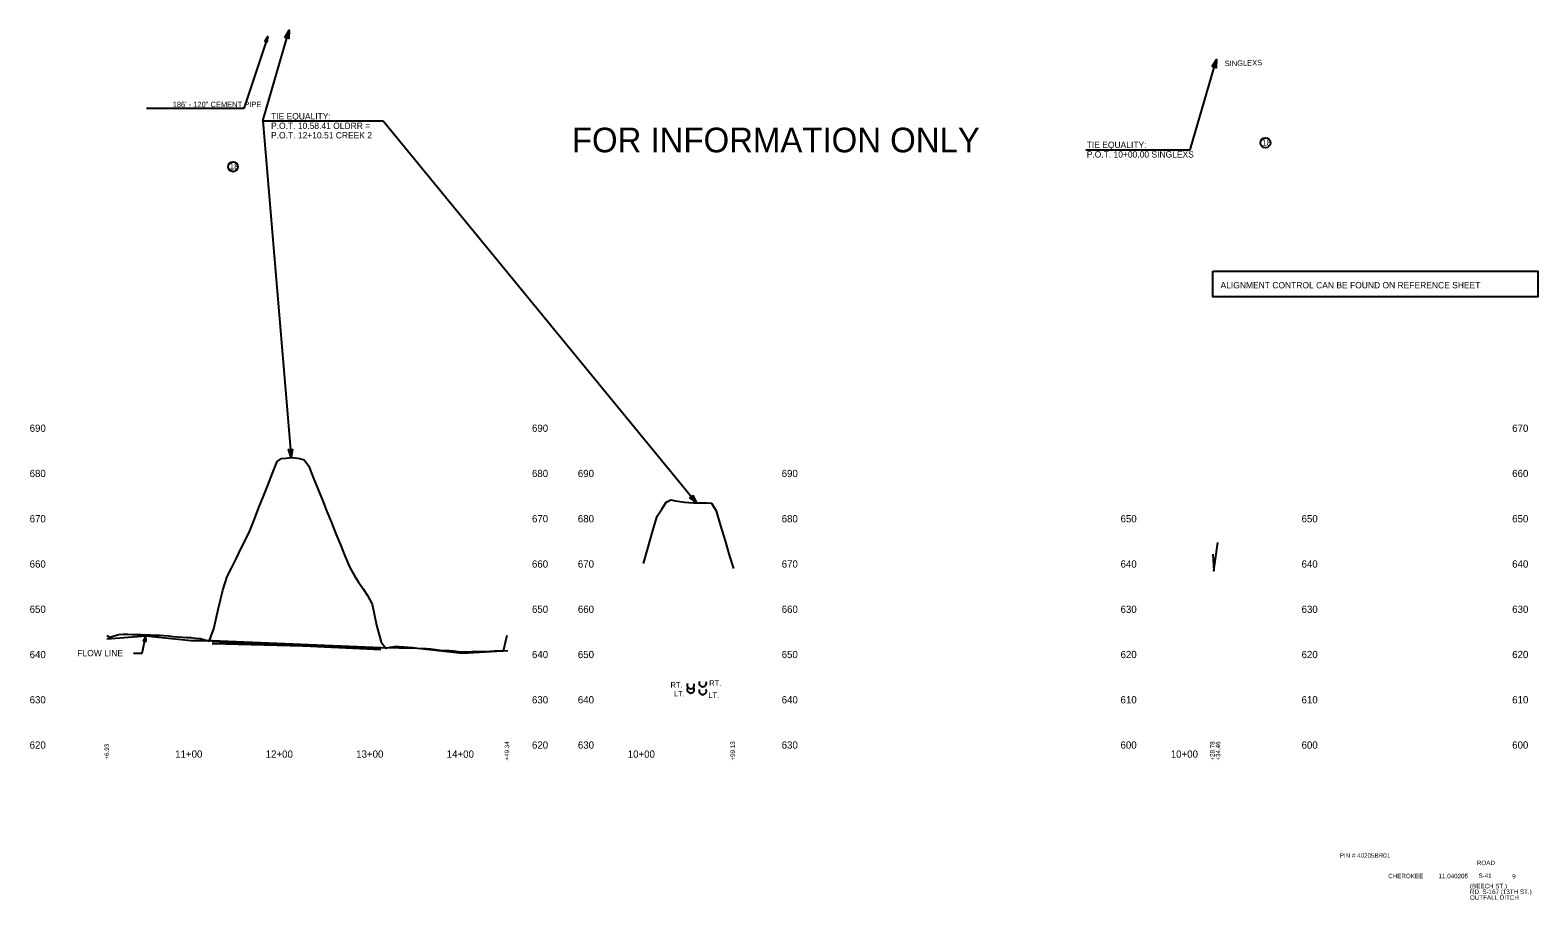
# Model space of a CAD drawing. Extents: x 16382402 to 16388022, y 46194326 to 46202918.
# Drawn here: x 16384274 to 16385939, y 46198905 to 46199866 of the extents above; entities that cross this region are included whole.
import ezdxf

# ---------------------------------------------------------------- set-up
doc = ezdxf.new("R2010")
doc.units = 0
for name, color, linetype in [('Default', 7, 'Continuous'), ('RD_DDB_ElevTX', 7, 'Continuous'), ('RD_DDB_Profile_EX', 7, 'Continuous'), ('RD_DDB_Profile_Lbl', 7, 'Continuous'), ('RD_DDB_StaTX', 7, 'Continuous'), ('RD_EX_DR_Pipe', 7, 'Continuous'), ('RD_EX_DV_Prop', 7, 'Continuous'), ('RD_EX_Misc', 7, 'Continuous'), ('RD_HC_Data', 7, 'Continuous'), ('RD_PD_Final_TX', 7, 'Continuous'), ('RD_Sketch1', 7, 'Continuous'), ('RD_TX_Drainage', 7, 'Continuous'), ('RD_TX_Misc1', 7, 'Continuous'), ('RD_TX_RoadID', 7, 'Continuous')]:
    doc.layers.add(name, color=color, linetype=linetype)

msp = doc.modelspace()

# ---------------------------------------------------------------- linework, layer by layer
at = {"layer": 'Default'}
for centre in [(16385003.4, 46199142), (16385016.7, 46199144.1), (16385003.4, 46199137.1), (16385016.7, 46199135.5)]:
    msp.add_arc(centre, 3.98, 153.828, 22.5332, dxfattribs=at)
at = {"layer": 'RD_DDB_Profile_EX'}
for points in [[(16384358.3, 46199196.8), (16384361.4, 46199195.1), (16384366.4, 46199196.5), (16384371.4, 46199197.9), (16384376.4, 46199198.4), (16384381.4, 46199198.1), (16384386.4, 46199197.8), (16384391.4, 46199197.8), (16384396.4, 46199197.8), (16384401.4, 46199197.7), (16384406.4, 46199197.5), (16384411.4, 46199197.3), (16384416.4, 46199197), (16384421.4, 46199196.7), (16384426.4, 46199196.3), (16384431.4, 46199195.7), (16384436.4, 46199195.2), (16384441.4, 46199194.9), (16384446.4, 46199194.7), (16384451.4, 46199194.5), (16384456.4, 46199194), (16384461.4, 46199193.4), (16384466.4, 46199192.2), (16384471.4, 46199190.6), (16384476.4, 46199204), (16384481.4, 46199225.5), (16384486.4, 46199247), (16384491.4, 46199261.8), (16384496.4, 46199272), (16384501.4, 46199282.2), (16384506.4, 46199292.4), (16384511.4, 46199302.6), (16384516.4, 46199312.6), (16384521.4, 46199325.4), (16384526.4, 46199338.1), (16384531.4, 46199350.9), (16384536.4, 46199363.6), (16384541.4, 46199376.3), (16384546.4, 46199389.2), (16384551.4, 46199392.3), (16384556.4, 46199392.8), (16384561.4, 46199393.4), (16384566.4, 46199392.9), (16384571.4, 46199392.2), (16384576.4, 46199390.9), (16384581.4, 46199383.7), (16384586.4, 46199371.3), (16384591.4, 46199358.8), (16384596.4, 46199346.4), (16384601.4, 46199333.9), (16384606.4, 46199321.5), (16384611.4, 46199309.2), (16384616.4, 46199297), (16384621.4, 46199284.8), (16384626.4, 46199272.6), (16384631.4, 46199263.3), (16384636.4, 46199255.9), (16384641.4, 46199248.5), (16384646.4, 46199240.9), (16384651.4, 46199231.4), (16384656.4, 46199208.4), (16384661.4, 46199189.6), (16384666.4, 46199182.9), (16384671.4, 46199183.8), (16384676.4, 46199184.6), (16384681.4, 46199184.7), (16384686.4, 46199184.4), (16384691.4, 46199184), (16384696.4, 46199183.4), (16384701.4, 46199182.9), (16384706.4, 46199182.5), (16384711.4, 46199182.3), (16384716.4, 46199181.9), (16384721.4, 46199181.3), (16384726.4, 46199180.7), (16384731.4, 46199180.4), (16384736.4, 46199180.2), (16384741.4, 46199179.9), (16384746.4, 46199179.2), (16384751.4, 46199178.6), (16384756.4, 46199178.9), (16384761.4, 46199179.3), (16384766.4, 46199179.4), (16384771.4, 46199179.3), (16384776.4, 46199179.3), (16384781.4, 46199179.5), (16384786.4, 46199179.9), (16384791.4, 46199180), (16384796.4, 46199179.9), (16384800.7, 46199197.3)], [(16384951.4, 46199276.2), (16384956.4, 46199294.5), (16384961.4, 46199312.9), (16384966.4, 46199328.8), (16384971.4, 46199336.5), (16384976.4, 46199344.2), (16384981.4, 46199346.5), (16384986.4, 46199345.7), (16384991.4, 46199344.9), (16384996.4, 46199344.1), (16385001.4, 46199343.6), (16385006.4, 46199343.5), (16385011.4, 46199343.4), (16385016.4, 46199343.3), (16385021.4, 46199343.2), (16385026.4, 46199343.1), (16385031.4, 46199334.5), (16385036.4, 46199317.9), (16385041.4, 46199301.3), (16385046.4, 46199284.6), (16385050.5, 46199270.9)], [(16385580.1, 46199286.7), (16385581.4, 46199268.2), (16385585.8, 46199299.5)], [(16384358.3, 46199193), (16384401.4, 46199196.3), (16384451.4, 46199191.2), (16384474.5, 46199191.2), (16384661.1, 46199183.4), (16384701.4, 46199182.9), (16384751.4, 46199177.2), (16384801.4, 46199180.1)]]:
    msp.add_lwpolyline(points, dxfattribs=at)
at = {"layer": 'RD_EX_DR_Pipe'}
for p, q in [((16384474.5, 46199190.1), (16384661.1, 46199181.5)), ((16384474.5, 46199188.1), (16384661.1, 46199183.2))]:
    msp.add_line(p, q, dxfattribs=at)
at = {"layer": 'RD_EX_DV_Prop'}
for centre in [(16385638.4, 46199741.1), (16384497.7, 46199714.7)]:
    msp.add_circle(centre, 5.49, dxfattribs=at)
at = {"layer": 'RD_HC_Data'}
for p, q in [((16384530.5, 46199765.5), (16384559.8, 46199865.5)), ((16385555.1, 46199733.2), (16385584.3, 46199833.3)), ((16384530.5, 46199765.5), (16384663.5, 46199765.5)), ((16384530.5, 46199765.5), (16384561.9, 46199393.3)), ((16384663.5, 46199765.5), (16385009.8, 46199343.4)), ((16385439.8, 46199733.2), (16385555.1, 46199733.2))]:
    msp.add_line(p, q, dxfattribs=at)
at = {"layer": 'RD_Sketch1'}
msp.add_lwpolyline([(16385580.2, 46199599.2), (16385939.4, 46199599.2), (16385939.4, 46199570.8), (16385580.2, 46199570.8)], close=True, dxfattribs=at)
at = {"layer": 'RD_TX_Drainage'}
for p, q in [((16384536, 46199858.5), (16384509.8, 46199779)), ((16384509.8, 46199779), (16384402.2, 46199779))]:
    msp.add_line(p, q, dxfattribs=at)
for points in [[(16384535.7, 46199852.6), (16384536, 46199858.5), (16384532.7, 46199853.5)], [(16384555.1, 46199857.5), (16384559.8, 46199865.5), (16384559.4, 46199856.3)], [(16385579.7, 46199825.3), (16385584.3, 46199833.3), (16385584, 46199824)], [(16384563.3, 46199402.5), (16384561.9, 46199393.3), (16384558.9, 46199402.1)], [(16385005.8, 46199351.8), (16385009.8, 46199343.4), (16385002.3, 46199348.9)], [(16384401.6, 46199190.3), (16384401.4, 46199196.3), (16384398.6, 46199191)]]:
    msp.add_lwpolyline(points, close=True, dxfattribs=at)
at = {"layer": 'RD_TX_Misc1'}
for p, q in [((16384397.2, 46199177.2), (16384401.4, 46199196.3)), ((16384387.9, 46199177.2), (16384397.2, 46199177.2))]:
    msp.add_line(p, q, dxfattribs=at)

# ---------------------------------------------------------------- texts
at = {"layer": 'Default'}
for s, p in [('RT.', (16384981.1, 46199139.3)), ('RT.', (16385023.8, 46199141.3)), ('LT.', (16384984.8, 46199129.5)), ('LT.', (16385022.8, 46199127.9))]:
    msp.add_text(s, height=6, dxfattribs=at).set_placement(p)
at = {"layer": 'RD_DDB_ElevTX'}
for s, p in [('690', (16384273, 46199421.8)), ('690', (16384828, 46199421.8)), ('670', (16385911, 46199421.8)), ('680', (16384273, 46199371.8)), ('680', (16384828, 46199371.8)), ('690', (16384878.7, 46199371.8)), ('690', (16385103.9, 46199371.8)), ('660', (16385911, 46199371.8)), ('670', (16384273, 46199321.8)), ('670', (16384828, 46199321.8)), ('680', (16384878.7, 46199321.8)), ('680', (16385103.9, 46199321.8)), ('650', (16385478.3, 46199321.8)), ('650', (16385678.3, 46199321.8)), ('650', (16385911, 46199321.8)), ('660', (16384273, 46199271.8)), ('660', (16384828, 46199271.8)), ('670', (16384878.7, 46199271.8)), ('670', (16385103.9, 46199271.8)), ('640', (16385478.3, 46199271.8)), ('640', (16385678.3, 46199271.8)), ('640', (16385911, 46199271.8)), ('650', (16384273, 46199221.8)), ('650', (16384828, 46199221.8)), ('660', (16384878.7, 46199221.8)), ('660', (16385103.9, 46199221.8)), ('630', (16385478.3, 46199221.8)), ('630', (16385678.3, 46199221.8)), ('630', (16385911, 46199221.8)), ('640', (16384273, 46199171.8)), ('640', (16384828, 46199171.8)), ('650', (16384878.7, 46199171.8)), ('650', (16385103.9, 46199171.8)), ('620', (16385478.3, 46199171.8)), ('620', (16385678.3, 46199171.8)), ('620', (16385911, 46199171.8)), ('630', (16384273, 46199121.8)), ('630', (16384828, 46199121.8)), ('640', (16384878.7, 46199121.8)), ('640', (16385103.9, 46199121.8)), ('610', (16385478.3, 46199121.8)), ('610', (16385678.3, 46199121.8)), ('610', (16385911, 46199121.8)), ('620', (16384273, 46199071.8)), ('620', (16384828, 46199071.8)), ('630', (16384878.7, 46199071.8)), ('630', (16385103.9, 46199071.8)), ('600', (16385478.3, 46199071.8)), ('600', (16385678.3, 46199071.8)), ('600', (16385911, 46199071.8))]:
    msp.add_text(s, height=8, dxfattribs=at).set_placement(p)
at = {"layer": 'RD_DDB_Profile_Lbl'}
msp.add_text('FLOW LINE', height=7, dxfattribs=at).set_placement((16384325.7, 46199173.9))
at = {"layer": 'RD_DDB_StaTX'}
for s, p in [('+6.93', (16384360.7, 46199059.7)), ('+49.34', (16384802.8, 46199058.6)), ('+99.13', (16385052.3, 46199058.6)), ('+28.78', (16385582.2, 46199058.6)), ('+34.46', (16385588.5, 46199058.5))]:
    msp.add_text(s, height=5, rotation=90, dxfattribs=at).set_placement(p)
for s, p in [('11+00', (16384433.8, 46199061.8)), ('12+00', (16384533.8, 46199061.8)), ('13+00', (16384633.8, 46199061.8)), ('14+00', (16384733.8, 46199061.8)), ('10+00', (16384933.8, 46199061.8)), ('10+00', (16385533.8, 46199061.8))]:
    msp.add_text(s, height=8, dxfattribs=at).set_placement(p)
at = {"layer": 'RD_EX_DV_Prop'}
for p in [(16385634.5, 46199738), (16384493.7, 46199711.6)]:
    msp.add_text('18', height=7, dxfattribs=at).set_placement(p)
at = {"layer": 'RD_EX_Misc'}
for s, p in [('PIN # 40205BR01', (16385720.5, 46198951.3)), ('ROAD', (16385872, 46198943.1)), ('CHEROKEE', (16385774, 46198928.6)), ('11.040205 ', (16385829.6, 46198928.6)), ('S-41', (16385873.8, 46198928.9)), ('9', (16385911, 46198928.4)), ('OUTFALL DITCH ', (16385864.3, 46198904.8)), ('(BEECH ST.)', (16385864.3, 46198917.5)), ('RD. S-167 (13TH ST.)', (16385864.3, 46198911.2))]:
    msp.add_text(s, height=5, dxfattribs=at).set_placement(p)
at = {"layer": 'RD_HC_Data'}
for s, p in [('TIE EQUALITY:', (16384539.7, 46199766.9)), ('P.O.T. 10.58.41 OLDRR =', (16384539.7, 46199756.4)), ('P.O.T. 12+10.51 CREEK 2', (16384539.7, 46199745.9)), ('TIE EQUALITY:', (16385440.9, 46199735.3)), ('P.O.T. 10+00.00 SINGLEXS', (16385440.9, 46199724.8))]:
    msp.add_text(s, height=7, dxfattribs=at).set_placement(p)
at = {"layer": 'RD_PD_Final_TX'}
msp.add_text('FOR INFORMATION ONLY', height=27.205, dxfattribs=at).set_placement((16384872.1, 46199730.6))
at = {"layer": 'RD_Sketch1'}
msp.add_text('ALIGNMENT CONTROL CAN BE FOUND ON REFERENCE SHEET', height=7, dxfattribs=at).set_placement((16385588.8, 46199580.3))
at = {"layer": 'RD_TX_Drainage'}
msp.add_text('     186\' - 120" CEMENT PIPE', height=6, dxfattribs=at).set_placement((16384419.5, 46199780.5))
at = {"layer": 'RD_TX_RoadID'}
msp.add_text('SINGLEXS', height=6, rotation=1.5705, dxfattribs=at).set_placement((16385593.4, 46199825.7))

doc.saveas('drawing.dxf')
